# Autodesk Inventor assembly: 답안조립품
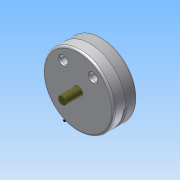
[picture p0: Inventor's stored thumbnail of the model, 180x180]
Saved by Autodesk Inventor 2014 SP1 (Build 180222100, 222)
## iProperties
Created: 2015-05
Part Number: 답안조립품
Document SubType Name: Assembly
Designer: 상담실
Author: 상담실
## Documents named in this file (10)
- C:\Users\상담실\Desktop\Inventor2급\Inventor2급-고미혜\답안조립품.iam
- C:\Users\상담실\Desktop\Inventor2급\Inventor2급-고미혜\본체.ipt
- C:\Users\상담실\Desktop\Inventor2급\Inventor2급-고미혜\축.ipt
- C:\Users\상담실\Desktop\Inventor2급\Inventor2급-고미혜\멈춤링.ipt
- C:\Users\상담실\Desktop\Inventor2급\Inventor2급-고미혜\베어링62_22.ipt
- C:\Users\상담실\Desktop\Inventor2급\Inventor2급-고미혜\덮개.ipt
- C:\Users\상담실\Desktop\Inventor2급\Inventor2급-고미혜\슬라이더2.ipt
- C:\Users\상담실\Desktop\Inventor2급\Inventor2급-고미혜\슬라이더.ipt
- C:\Users\상담실\Desktop\Inventor2급\Inventor2급-고미혜\M 10 x 35.ipt
- C:\Users\상담실\Desktop\Inventor2급\Inventor2급-고미혜\평행핀.ipt
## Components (2 placed, 1 different names)
1. M 10 x 35:1
2. M 10 x 35:2
